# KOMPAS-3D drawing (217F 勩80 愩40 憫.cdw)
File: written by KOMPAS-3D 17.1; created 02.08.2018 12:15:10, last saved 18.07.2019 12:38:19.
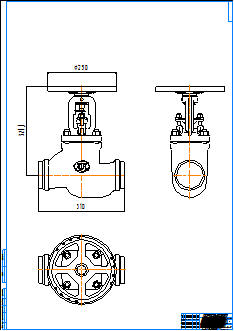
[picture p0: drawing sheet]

Sheet 1: A0, portrait

Title block, sheet 1: name: 217F Ду80 Ру40 СС; material: Внимание! Данный продукт является объектом авторского права ООО «Торговый Дом АДЛ». / Запрещается изменение, копирование, распространение / (в том числе путем копирования на другие сайты и ресурсы в Интернете) / или любое иное использование информации и объектов без предварительного / согласия правообладателя (ООО «Торговый Дом АДЛ»).; sheets: 1; organisation: ООО "Торговый дом АДЛ"; sheet format: A0; stored path: \\adlc.lan\data\АДЛ_ПКД\3D-модели\Поставщики\Zetkama\Вентили\217F\KOMPAS 2D\217F Ду80 Ру40 СС.cdw

Views: Вид 1, Проекционный вид 2, Проекционный вид 3
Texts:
  kka
  adl
Dimensions and other numbers on the sheet: 310; 321,1; 250; 1:1; 1; 217F Ду80 Ру40 СС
